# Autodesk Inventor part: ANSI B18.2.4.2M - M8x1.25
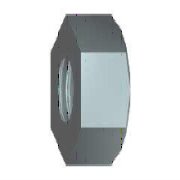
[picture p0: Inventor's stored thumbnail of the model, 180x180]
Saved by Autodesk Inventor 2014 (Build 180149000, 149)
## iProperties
IsCustomPart: 0
Created: 2008-02
Part Number: ANSI B18.2.4.2M - M8x1.25
Material: Steel, Mild
Description: Metric Hex Nuts
Document SubType Name: Modeling
Standard: ANSI B18.2.4.2M
Designer: PN
Standards Organization: ANSI
Language: en-US
Size Designation: M8x1.25
Categories: <MemberInstance><Categories><Category DisplayName="Fasteners" InternalName="e4da775c-781d-43d5-af7c-5136215cf5a6" Mnemonic="FSTN"><Category DisplayName="Nuts" I
Density: 7.86 g/cm^3
Mass: 6.47658 g
Surface Area: 6.89688 cm^2
Volume: 0.823992 cm^3
Appearance: Steel
Author: PN
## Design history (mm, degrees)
sketch "Sketch1"
  geometry: L1 (6.5, 3.753)-(6.5, -3.753); L2 (6.5, -3.753)-(0, -7.506); L3 (0, -7.506)-(-6.5, -3.753); L4 (-6.5, -3.753)-(-6.5, 3.753); L5 (-6.5, 3.753)-(0, 7.506); L6 (0, 7.506)-(6.5, 3.753); C1 r 6.5 at (0, 0); 2 further points
  constraints: 12 end point, 2 coincident, 1 centre point, 1 tangent, 1 vertical, 11 other
  dimensions: "d0" = 13 diameter of C1 (= Smax)
extrude "Extrusion1" new body sketch "Sketch1" distance "d1" = 7.5 (= Mmax); taper "d2" = 0 deg
chamfer "Chamfer1" distance "d10" = 0.625 (= 0.5 x PTC); stored, may be unused: second distance "d11" = 2, angle "d12" = 45 deg
sketch "Sketch3"
  geometry: L1 (-9.171, 0)-(2.529, 0) reference; L2 (-5.705, 0)-(0.857, 0); L3 (-7.5, 0)-(-7.5, -7.506); L4 (-7.5, -7.506)-(0, -7.506); L5 (0, -7.506)-(0, 0); L6 (-7.5, -3.753)-(-7.5, -7.506) reference; L7 (0, -3.753)-(0, -7.506) reference; L8 (0, -7.506)-(-7.5, -7.506) reference; L9 (-7.5, -6.5)-(-6.919, -7.506); L10 (-7.5, -7.506)-(-7.5, -6.5); L11 (-7.5, -7.506)-(-6.919, -7.506); L12 (0, -6.5)-(-0.581, -7.506); L13 (-0.581, -7.506)-(0, -7.506); L14 (0, -7.506)-(0, -6.5)
  constraints: 21 end point, 6 point on line, 5 collinear, 4 vertical, 3 equal length, 2 horizontal
  dimensions: "d32" = 6.5 distance from line of L9.start L1 (= 0.5 x Smax); "d33" = 30 deg angle of L9 L3
revolve "Revolution1" sketch "Sketch3" stored, may be unused: angle "d15" = 90 deg
node "MSC_A1"
node "MSC_PT1"
node "MSC_PT2"
node "MSC_PF1"
body "Solid1"
sketch "Sketch2"
  geometry: L1 (-6.5, 3.753)-(0, 7.506) reference; L2 (0, -7.506)-(-6.5, -3.753) reference; L3 (-6.5, 3.753)-(6.5, -3.753); L4 (-6.5, -3.753)-(6.5, 3.753); 1 further point
  constraints: 4 end point, 2 midpoint, 2 parallel
hole "Hole1" sketch "Sketch2" diameter "d3" = 6.647; stored, may be unused: countersink angle "d7" = 90 deg, drill point angle "d9" = 118 deg; dims "d4" = 6, "d5" = 4, "d6" = 2, "d8" = 8
other parameters: "NND" = 8 [user parameter; used in 1 equation term], "Smax" = 13 [user parameter; used in 2 equation terms], "Mmax" = 7.5 [user parameter; used in 1 equation term], "PTC" = 1.25 [user parameter; used in 1 equation term], "d16" = 0, "d17" = 0, "d18" = 0, "d19" = 0, "d21" = 0, "d22" = 0, "d23" = 0, "THREADDIA" = 8 (= NND) [user parameter], "TEMPLATE" = 12.345 [user parameter]
